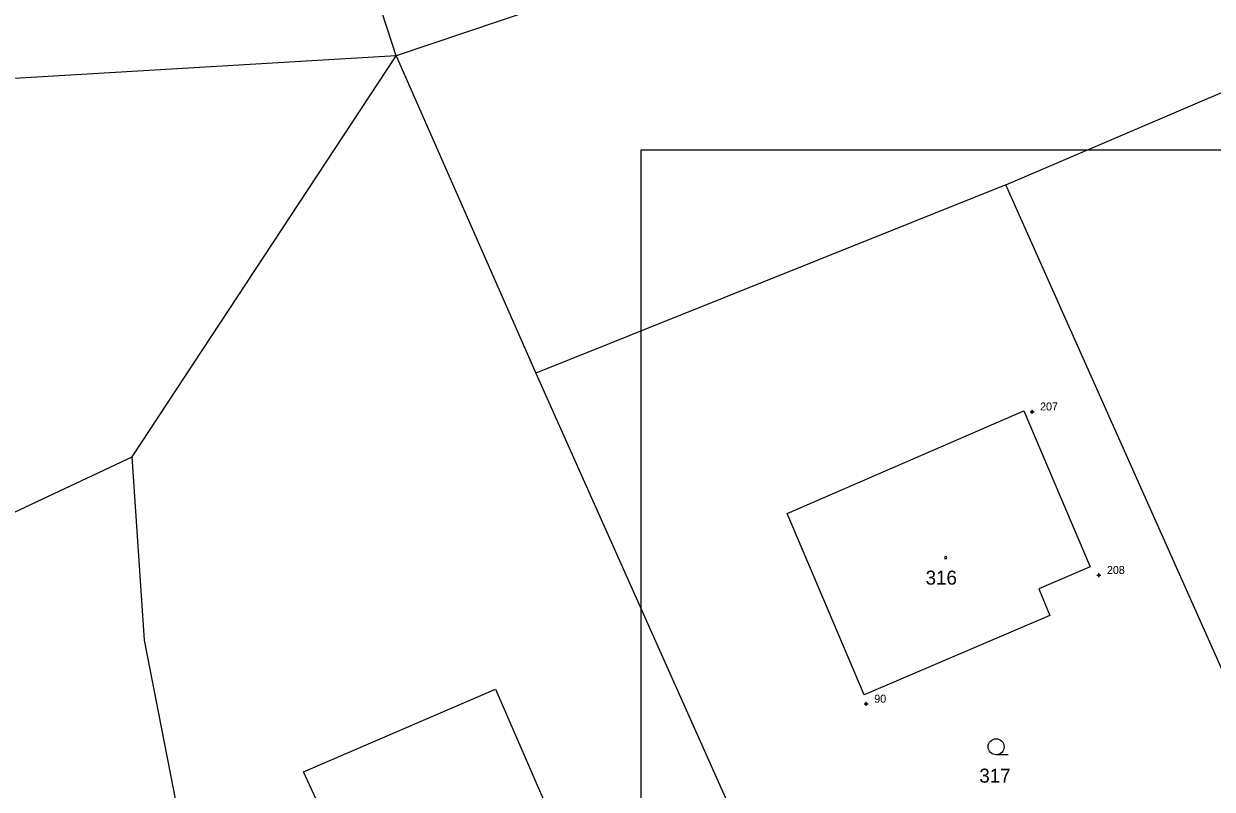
# Model space of a CAD drawing. Extents: x -454285 to -453563, y -1108687 to -1108249.
# Drawn here: x -454078.1 to -454018.7, y -1108501.8 to -1108463.6 of the extents above; entities that cross this region are included whole.
import ezdxf

# ---------------------------------------------------------------- set-up
doc = ezdxf.new("R2010")
doc.units = 0
for name, color, linetype in [('1', 7, 'Continuous'), ('14', 7, 'Continuous'), ('15', 7, 'Continuous'), ('23', 7, 'Continuous'), ('25', 7, 'Continuous'), ('BODY_T1_2018', 7, 'Continuous'), ('CISLA_T1_2018', 7, 'Continuous'), ('rámy', 7, 'Continuous')]:
    doc.layers.add(name, color=color, linetype=linetype)

# ---------------------------------------------------------------- blocks, each defined once
blk = doc.blocks.new('Z402')
for start, end in [(0, 180), (180, 0)]:
    blk.add_arc((0, 0), 0.15, start, end)
blk = doc.blocks.new('Z3040')
blk.add_line((1.5, 0), (0, 0))
blk.add_circle((0, 1), 1)
blk = doc.blocks.new('POINT_DISPLAY')
for p, q in [((-0.1, 0), (0.1, 0)), ((0, -0.1), (0, 0.1))]:
    blk.add_line(p, q)
blk.add_circle((0, 0), 0.05)
blk = doc.blocks.new('t1_2018')
at = {"layer": 'BODY_T1_2018'}
for p in [(-454027.68, -1108482.94), (-454024.34, -1108491.11), (-454035.97, -1108497.54)]:
    blk.add_blockref('POINT_DISPLAY', p, dxfattribs=at)
at = {"layer": 'CISLA_T1_2018'}
for s, p in [('207', (-454027.28, -1108482.88)), ('208', (-454023.94, -1108491.05)), ('90', (-454035.57, -1108497.48))]:
    blk.add_text(s, height=0.4, dxfattribs=at).set_placement(p)

msp = doc.modelspace()

# ---------------------------------------------------------------- linework, layer by layer
at = {"layer": '1'}
for p, q in [((-454019.817, -1108451.781), (-454059.467, -1108465.161)), ((-454059.467, -1108465.161), (-454063.617, -1108452.521)), ((-454059.467, -1108465.161), (-454117.667, -1108468.621)), ((-454072.677, -1108485.191), (-454059.467, -1108465.161)), ((-454059.467, -1108465.161), (-454052.497, -1108481.021)), ((-454028.997, -1108471.611), (-454014.987, -1108465.611)), ((-454028.997, -1108471.611), (-454052.497, -1108481.021)), ((-454015.197, -1108502.531), (-454028.997, -1108471.611)), ((-454052.497, -1108481.021), (-454038.597, -1108512.101)), ((-454039.927, -1108488.031), (-454028.097, -1108482.891)), ((-454028.097, -1108482.891), (-454024.777, -1108490.691)), ((-454103.897, -1108499.911), (-454072.677, -1108485.191)), ((-454072.057, -1108494.361), (-454072.677, -1108485.191)), ((-454036.077, -1108497.081), (-454039.927, -1108488.031)), ((-454024.777, -1108490.691), (-454027.347, -1108491.791)), ((-454027.347, -1108491.791), (-454026.787, -1108493.121)), ((-454026.787, -1108493.121), (-454036.077, -1108497.081)), ((-454066.217, -1108523.991), (-454072.057, -1108494.361)), ((-454064.107, -1108500.931), (-454054.507, -1108496.801)), ((-454054.507, -1108496.801), (-454050.047, -1108507.081)), ((-454059.987, -1108509.811), (-454064.107, -1108500.931))]:
    msp.add_line(p, q, dxfattribs=at)
at = {"layer": 'rámy'}
msp.add_lwpolyline([(-454047.225, -1108469.854), (-453948.057, -1108469.854), (-453948.057, -1108529.906), (-454047.225, -1108529.906)], close=True, dxfattribs=at)

# ---------------------------------------------------------------- block references
msp.add_blockref('t1_2018', (0, 0))
at = {"layer": '23', "xscale": 0.4, "yscale": 0.4000000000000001}
msp.add_blockref('Z3040', (-454029.477, -1108500.081), dxfattribs=at)
at = {"layer": '25', "xscale": 0.4, "yscale": 0.4000000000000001}
msp.add_blockref('Z402', (-454032.007, -1108490.232), dxfattribs=at)

# ---------------------------------------------------------------- texts
at = {"layer": '14'}
msp.add_text('317', height=0.7, dxfattribs=at).set_placement((-454030.318, -1108501.475))
at = {"layer": '15'}
msp.add_text('316', height=0.7, dxfattribs=at).set_placement((-454033.003, -1108491.581))

doc.saveas('drawing.dxf')
